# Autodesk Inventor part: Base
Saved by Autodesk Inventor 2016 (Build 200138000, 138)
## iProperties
Created: 2016-01
Part Number: Base
Material: Generic
Document SubType Name: Modeling
Designer: John
Density: 1 g/cm^3
Appearance: Default
Author: John
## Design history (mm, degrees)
feature "Base1"
body "Solid1"
